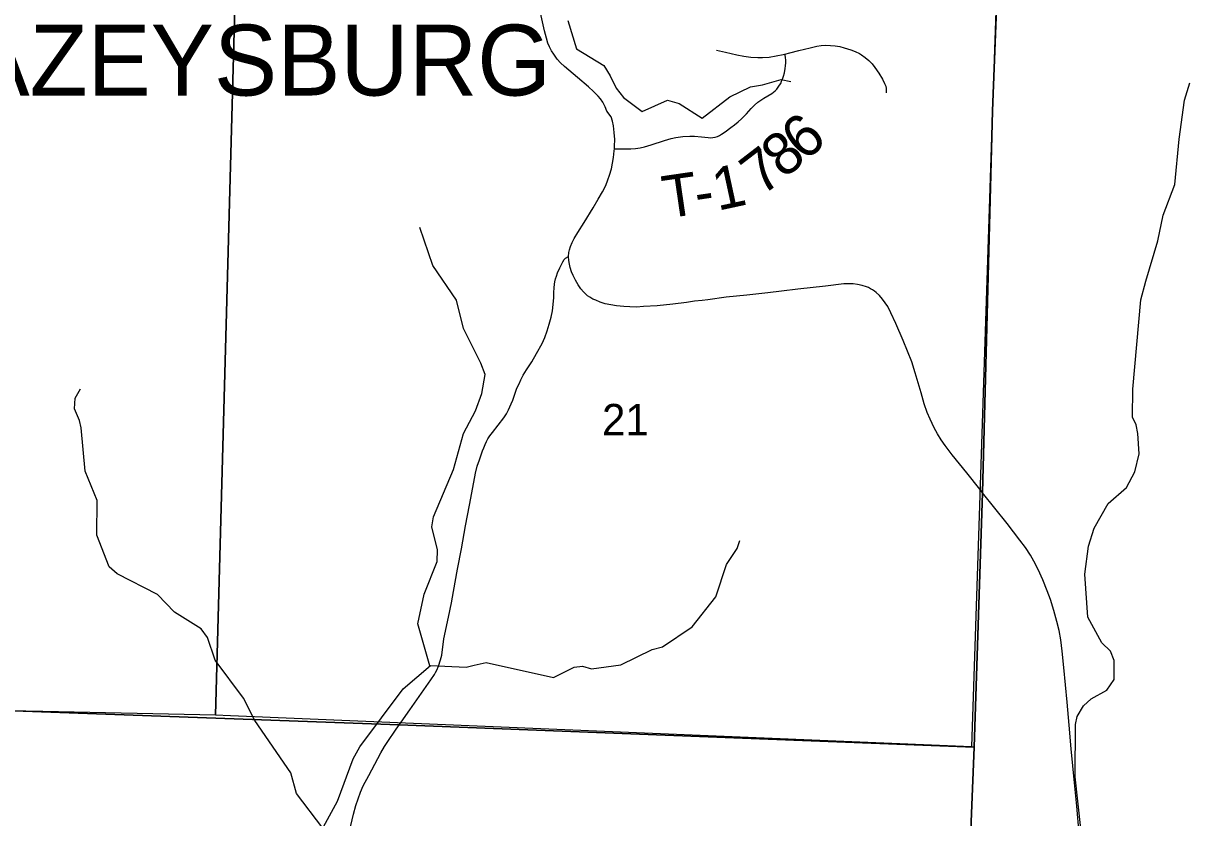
# Model space of a CAD drawing. Extents: x 0 to 34, y 0 to 22.
# Drawn here: x 4.796 to 6.364, y 16.31 to 17.372 of the extents above; entities that cross this region are included whole.
import ezdxf

# ---------------------------------------------------------------- set-up
doc = ezdxf.new("R2010")
doc.units = 0
for name, color, linetype in [('GM_X_Corporation_Text', 7, 'Continuous'), ('GM_X_County_Road', 7, 'Continuous'), ('GM_X_Minor_River', 7, 'Continuous'), ('GM_X_Section', 7, 'Continuous'), ('GM_X_Section_Text', 7, 'Continuous'), ('GM_X_Township', 7, 'Continuous'), ('GM_X_Township_Road', 7, 'Continuous'), ('GM_X_Township_Road_Text', 7, 'Continuous')]:
    doc.layers.add(name, color=color, linetype=linetype)

msp = doc.modelspace()

# ---------------------------------------------------------------- linework, layer by layer
at = {"layer": 'GM_X_County_Road'}
for points in [[(5.5859, 17.2042), (5.5861, 17.2076), (5.5862, 17.2167), (5.5856, 17.2259), (5.5844, 17.235), (5.5831, 17.2409), (5.5814, 17.2468), (5.5759, 17.2545), (5.5737, 17.2604), (5.5702, 17.2666), (5.5674, 17.2707), (5.564, 17.2746), (5.5581, 17.2808), (5.5511, 17.287), (5.5366, 17.2994), (5.5191, 17.3143), (5.5137, 17.3191), (5.5094, 17.3239), (5.5047, 17.3304), (5.5017, 17.3352), (5.4993, 17.3402), (5.4971, 17.3454), (5.4949, 17.3521), (5.4924, 17.3618), (5.487, 17.3859)], [(5.5245, 17.06), (5.5251, 17.0655), (5.526, 17.0691), (5.5273, 17.0736), (5.5294, 17.0789), (5.5322, 17.084), (5.5369, 17.0921), (5.5454, 17.1055), (5.5574, 17.1254), (5.5642, 17.1366), (5.5699, 17.1468), (5.5744, 17.1552), (5.5772, 17.1625), (5.5794, 17.169), (5.5821, 17.1771), (5.5845, 17.1924), (5.5857, 17.2015), (5.5859, 17.2042)], [(6.074, 16.749), (6.0566, 16.771), (6.0372, 16.7951), (6.0278, 16.8075), (6.0225, 16.8152), (6.0176, 16.8231), (6.0131, 16.8313), (6.0078, 16.8425), (6.0039, 16.8515), (5.9997, 16.8634), (5.9956, 16.8777), (5.9879, 16.9045), (5.9831, 16.9192), (5.9776, 16.9337), (5.9717, 16.948), (5.9618, 16.9708), (5.9554, 16.985), (5.9511, 16.9932), (5.9478, 16.9984), (5.9442, 17.0033), (5.9401, 17.0078), (5.9356, 17.012), (5.9332, 17.0139), (5.9307, 17.0156), (5.9281, 17.0171), (5.9253, 17.0185), (5.9225, 17.0197), (5.9168, 17.0215), (5.9108, 17.0228), (5.9047, 17.0235), (5.8986, 17.0237), (5.8925, 17.0234), (5.8678, 17.0207), (5.8308, 17.0165), (5.8093, 17.014), (5.7908, 17.0117), (5.7629, 17.0086), (5.7351, 17.0056), (5.7105, 17.0023), (5.7033, 17.0014), (5.6928, 17.0003), (5.6821, 16.9988), (5.6638, 16.9966), (5.6428, 16.9944), (5.6248, 16.9931), (5.6155, 16.9926), (5.6063, 16.9928), (5.5984, 16.9931), (5.5888, 16.9942), (5.581, 16.9954), (5.5737, 16.997), (5.5667, 16.9991), (5.561, 17.0016), (5.5571, 17.0033), (5.553, 17.0058), (5.5499, 17.0077), (5.5467, 17.0105), (5.5445, 17.013), (5.5411, 17.0167), (5.5372, 17.0224), (5.5338, 17.0284), (5.5309, 17.0346), (5.5287, 17.0396), (5.5269, 17.0453), (5.5257, 17.05), (5.525, 17.0548), (5.5245, 17.06)], [(6.2068, 16.2889), (6.2038, 16.3254), (6.2007, 16.3564), (6.1963, 16.4019), (6.1935, 16.4335), (6.1907, 16.4644), (6.1862, 16.5108), (6.1842, 16.5325), (6.1822, 16.5478), (6.18, 16.56), (6.1772, 16.5721), (6.173, 16.587), (6.1683, 16.6018), (6.1641, 16.6134), (6.1584, 16.6278), (6.1519, 16.6419), (6.1463, 16.6528), (6.1416, 16.6608), (6.1349, 16.6711), (6.1276, 16.6811), (6.1105, 16.7031), (6.0777, 16.7443), (6.074, 16.749)]]:
    msp.add_lwpolyline(points, dxfattribs=at)
at = {"layer": 'GM_X_Minor_River'}
for points in [[(5.5235, 17.3754), (5.535, 17.3375), (5.5719, 17.3153), (5.5803, 17.3016), (5.588, 17.285), (5.5979, 17.2725), (5.623, 17.254), (5.6567, 17.269), (5.6722, 17.2645), (5.703, 17.2449), (5.74, 17.2735), (5.7676, 17.2869), (5.7835, 17.2896), (5.8085, 17.2966), (5.8214, 17.294)], [(6.2092, 16.2956), (6.2013, 16.3646), (6.2018, 16.4344), (6.204, 16.4454), (6.2126, 16.4595), (6.2228, 16.4691), (6.2436, 16.4805), (6.2534, 16.4946), (6.2537, 16.52), (6.2487, 16.5325), (6.2373, 16.5439), (6.2185, 16.5779), (6.2145, 16.6356), (6.2192, 16.6731), (6.2267, 16.6971), (6.2455, 16.7298), (6.27, 16.7515), (6.2813, 16.7724), (6.2869, 16.7963), (6.2853, 16.8237), (6.2829, 16.835), (6.278, 16.8456), (6.2785, 16.8828), (6.2894, 17.0024), (6.2957, 17.027), (6.3121, 17.081), (6.3192, 17.1152), (6.3345, 17.1562), (6.3403, 17.2169), (6.3476, 17.2689), (6.3547, 17.2921)], [(5.3394, 16.513), (5.3233, 16.5691), (5.3315, 16.609), (5.3491, 16.6523), (5.3494, 16.6679), (5.342, 16.6989), (5.3439, 16.7122), (5.3709, 16.7753), (5.3843, 16.8235), (5.4001, 16.854), (5.4087, 16.8768), (5.4131, 16.9022), (5.4074, 16.9177), (5.3844, 16.9639), (5.3747, 17.0018), (5.3434, 17.048), (5.3258, 17.0991)], [(5.1964, 16.296), (5.161, 16.3423), (5.1537, 16.37), (5.1056, 16.4399), (5.0903, 16.4698), (5.0525, 16.5205), (5.0421, 16.5508), (5.0337, 16.5625), (4.998, 16.5848), (4.9755, 16.6082), (4.9216, 16.636), (4.9106, 16.6455), (4.8941, 16.6875), (4.8946, 16.7342), (4.8785, 16.7732), (4.8733, 16.8312), (4.871, 16.8411), (4.8645, 16.8566), (4.8655, 16.8706), (4.8723, 16.8832)], [(5.1946, 16.2927), (5.216, 16.3319), (5.2366, 16.3885), (5.2456, 16.4045), (5.3036, 16.4821), (5.3399, 16.5134), (5.3876, 16.5113), (5.3986, 16.5137), (5.4145, 16.5175), (5.5044, 16.4974), (5.532, 16.5112), (5.543, 16.5124), (5.5552, 16.509), (5.5942, 16.5145), (5.6362, 16.5348), (5.6502, 16.5386), (5.6898, 16.565), (5.7215, 16.6053), (5.7357, 16.6483), (5.75, 16.67), (5.7534, 16.6806)]]:
    msp.add_lwpolyline(points, dxfattribs=at)
at = {"layer": 'GM_X_Section'}
for points in [[(4.0746, 17.5111), (5.0805, 17.4591), (5.0528, 16.4469), (4.8222, 16.4519), (4.5034, 16.4581), (4.0244, 16.4784)], [(6.0962, 17.4141), (6.0907, 17.2474), (6.0735, 16.7271), (6.0629, 16.4049), (5.594, 16.4244), (5.073, 16.4461), (5.0528, 16.4469), (5.0805, 17.4591)]]:
    msp.add_lwpolyline(points, close=True, dxfattribs=at)
at = {"layer": 'GM_X_Township'}
for points in [[(2.6013, 16.5379), (2.8688, 16.5234), (3.5006, 16.5009), (4.2928, 16.4705), (5.2983, 16.434), (6.0664, 16.4042), (6.0777, 16.7443), (6.0911, 17.2548), (6.11, 17.7459), (6.1473, 18.845), (6.1717, 19.6397), (6.1731, 19.6616), (6.1731, 19.6818), (6.1733, 19.6859), (6.2234, 21.2003)], [(6.2234, 21.2003), (6.1733, 19.6859), (6.1731, 19.6818), (6.1731, 19.6616), (6.1717, 19.6397), (6.1473, 18.845), (6.11, 17.7459), (6.0911, 17.2548), (6.0777, 16.7443), (6.0664, 16.4042), (6.0598, 16.2379), (6.2085, 16.2337), (6.3056, 16.228), (6.5048, 16.2253), (7.5772, 16.1862), (7.7357, 16.1804), (8.4842, 16.1527), (8.5405, 16.1503), (9.1818, 16.131), (9.4013, 16.1226)], [(6.0598, 16.2379), (6.0664, 16.4042), (5.2983, 16.434), (4.2928, 16.4705)]]:
    msp.add_lwpolyline(points, dxfattribs=at)
at = {"layer": 'GM_X_Township_Road'}
for points in [[(5.7223, 17.3359), (5.7344, 17.3331), (5.7495, 17.3296), (5.7587, 17.3279), (5.768, 17.3267), (5.7773, 17.3261), (5.7835, 17.3261), (5.7928, 17.3268), (5.8021, 17.3282), (5.8112, 17.33), (5.8136, 17.3306)], [(5.8136, 17.3306), (5.8203, 17.3322), (5.8322, 17.3354), (5.8472, 17.3392), (5.8562, 17.3413), (5.8623, 17.3423), (5.8685, 17.3427), (5.8746, 17.3424), (5.8808, 17.3418), (5.8869, 17.3407), (5.8929, 17.3392), (5.9018, 17.3364), (5.9076, 17.3341), (5.9132, 17.3314), (5.9159, 17.3298), (5.921, 17.3263), (5.9257, 17.3223), (5.9301, 17.3178), (5.9339, 17.3129), (5.939, 17.3051), (5.9439, 17.2971), (5.9468, 17.2916), (5.9483, 17.2876), (5.9489, 17.2848), (5.9491, 17.2822), (5.9489, 17.2789)], [(5.5859, 17.2042), (5.5905, 17.2041), (5.6079, 17.2041), (5.6141, 17.2044), (5.6202, 17.2053), (5.6262, 17.2066), (5.6351, 17.2093), (5.6528, 17.2154), (5.6618, 17.218), (5.6679, 17.2193), (5.6772, 17.2205), (5.6865, 17.2212), (5.6928, 17.2211), (5.7021, 17.2203), (5.7113, 17.2191), (5.7144, 17.2189), (5.7174, 17.2192), (5.7206, 17.2197), (5.7235, 17.2207), (5.7261, 17.222), (5.7288, 17.2235), (5.7339, 17.2269), (5.7413, 17.2326), (5.7464, 17.2363), (5.7512, 17.2401), (5.7558, 17.2442), (5.7622, 17.2509), (5.7685, 17.2578), (5.7729, 17.2623), (5.7776, 17.2664), (5.7801, 17.2683), (5.7853, 17.2717), (5.7907, 17.2748), (5.796, 17.278), (5.7985, 17.2798), (5.8007, 17.2818), (5.8028, 17.284), (5.8047, 17.2864), (5.8064, 17.289), (5.808, 17.2916), (5.8093, 17.2943), (5.8105, 17.2971), (5.8119, 17.3012), (5.8129, 17.3057), (5.8141, 17.3116), (5.8146, 17.3152), (5.815, 17.3189), (5.8151, 17.3225), (5.8146, 17.3262), (5.8139, 17.3293), (5.8136, 17.3306)], [(5.3009, 16.4378), (5.3123, 16.4541), (5.3406, 16.4942), (5.3454, 16.5016), (5.347, 16.5043), (5.3484, 16.5073), (5.3507, 16.5126), (5.3535, 16.521), (5.3552, 16.5272), (5.358, 16.5493), (5.3642, 16.5781), (5.3681, 16.597), (5.3708, 16.6122), (5.3763, 16.6424), (5.3814, 16.6695), (5.387, 16.7002), (5.3921, 16.7279), (5.3979, 16.7584), (5.4003, 16.7706), (5.4026, 16.7797), (5.4054, 16.7885), (5.4097, 16.8003), (5.4113, 16.8046), (5.4131, 16.809), (5.4148, 16.8128), (5.4168, 16.8164), (5.4193, 16.8203), (5.4228, 16.8249), (5.4307, 16.8346), (5.4382, 16.8445), (5.4415, 16.8497), (5.4444, 16.8552), (5.4477, 16.863), (5.4499, 16.8682), (5.4533, 16.8773), (5.4552, 16.8828), (5.4568, 16.8866), (5.4584, 16.8901), (5.4609, 16.8955), (5.464, 16.9015), (5.4684, 16.9087), (5.4753, 16.9194), (5.4818, 16.9303), (5.4891, 16.9437), (5.4928, 16.9519), (5.4958, 16.9609), (5.4988, 16.9696), (5.5012, 16.9789), (5.5031, 16.9875), (5.5041, 16.9961), (5.5047, 17.0054), (5.5049, 17.0118), (5.5053, 17.0182), (5.5056, 17.0233), (5.5061, 17.0263), (5.5071, 17.0304), (5.5083, 17.034), (5.51, 17.0382), (5.5131, 17.0448), (5.517, 17.0531), (5.5187, 17.0562), (5.5195, 17.0572), (5.5205, 17.058), (5.5245, 17.06)], [(5.2313, 16.2904), (5.2371, 16.3145), (5.2403, 16.3265), (5.2433, 16.3353), (5.2466, 16.3441), (5.2502, 16.3524), (5.2575, 16.3665), (5.2739, 16.3967), (5.2787, 16.4052), (5.2838, 16.4132), (5.2924, 16.4256), (5.2983, 16.434), (5.3009, 16.4378)]]:
    msp.add_lwpolyline(points, dxfattribs=at)

# ---------------------------------------------------------------- texts
at = {"layer": 'GM_X_Corporation_Text'}
msp.add_text('FRAZEYSBURG', height=0.094697, rotation=0, dxfattribs=at).set_placement((4.5512, 17.2753))
at = {"layer": 'GM_X_Section_Text'}
msp.add_text('21', height=0.04186, rotation=0, dxfattribs=at).set_placement((5.5693, 16.8212))
at = {"layer": 'GM_X_Township_Road_Text'}
for s, rotation, p in [('6', 40.8509, (5.8399, 17.186)), ('8', 39.9482, (5.8123, 17.1629)), ('7', 37.5725, (5.7826, 17.1399)), ('1', 12.1943, (5.7237, 17.1211)), ('T', 8.3047, (5.6544, 17.1108)), ('-', 8.4254, (5.6966, 17.1169))]:
    msp.add_text(s, height=0.0568, rotation=rotation, dxfattribs=at).set_placement(p)

doc.saveas('drawing.dxf')
